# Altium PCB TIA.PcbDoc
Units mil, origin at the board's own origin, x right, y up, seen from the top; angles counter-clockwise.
Board outline 6000 x 4000 mil, 4 copper layers (Top Layer, GND, POWER, Bottom Layer), stack 23.756 mil thick; 19 components, 10 nets, 50 pads, 17 vias.
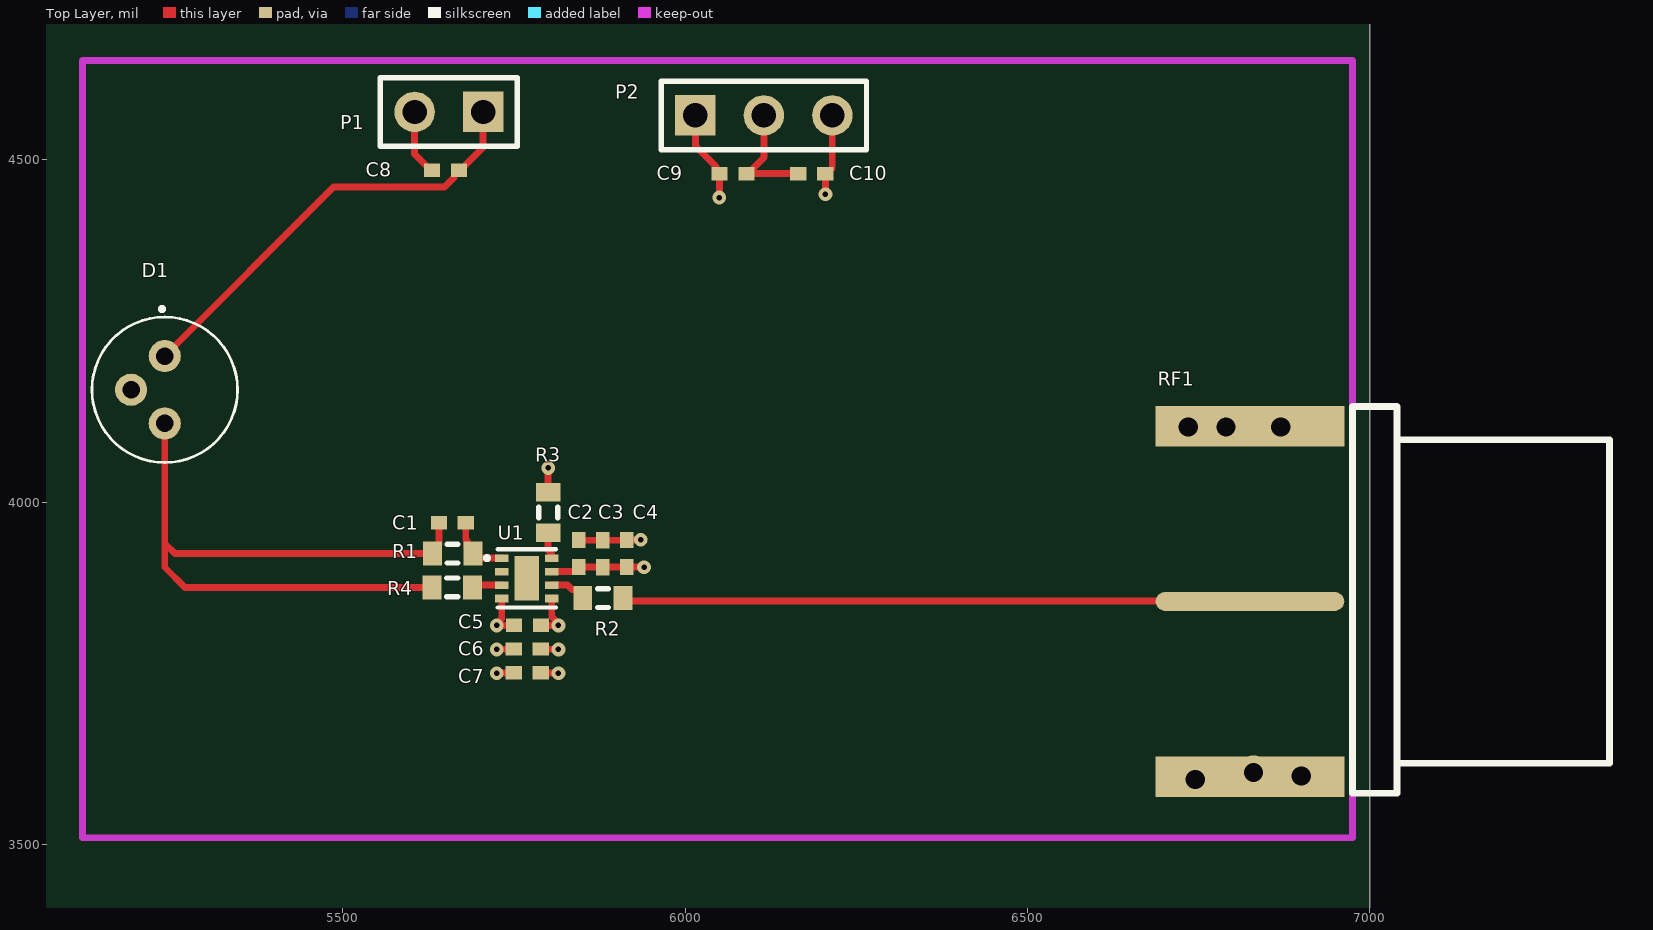
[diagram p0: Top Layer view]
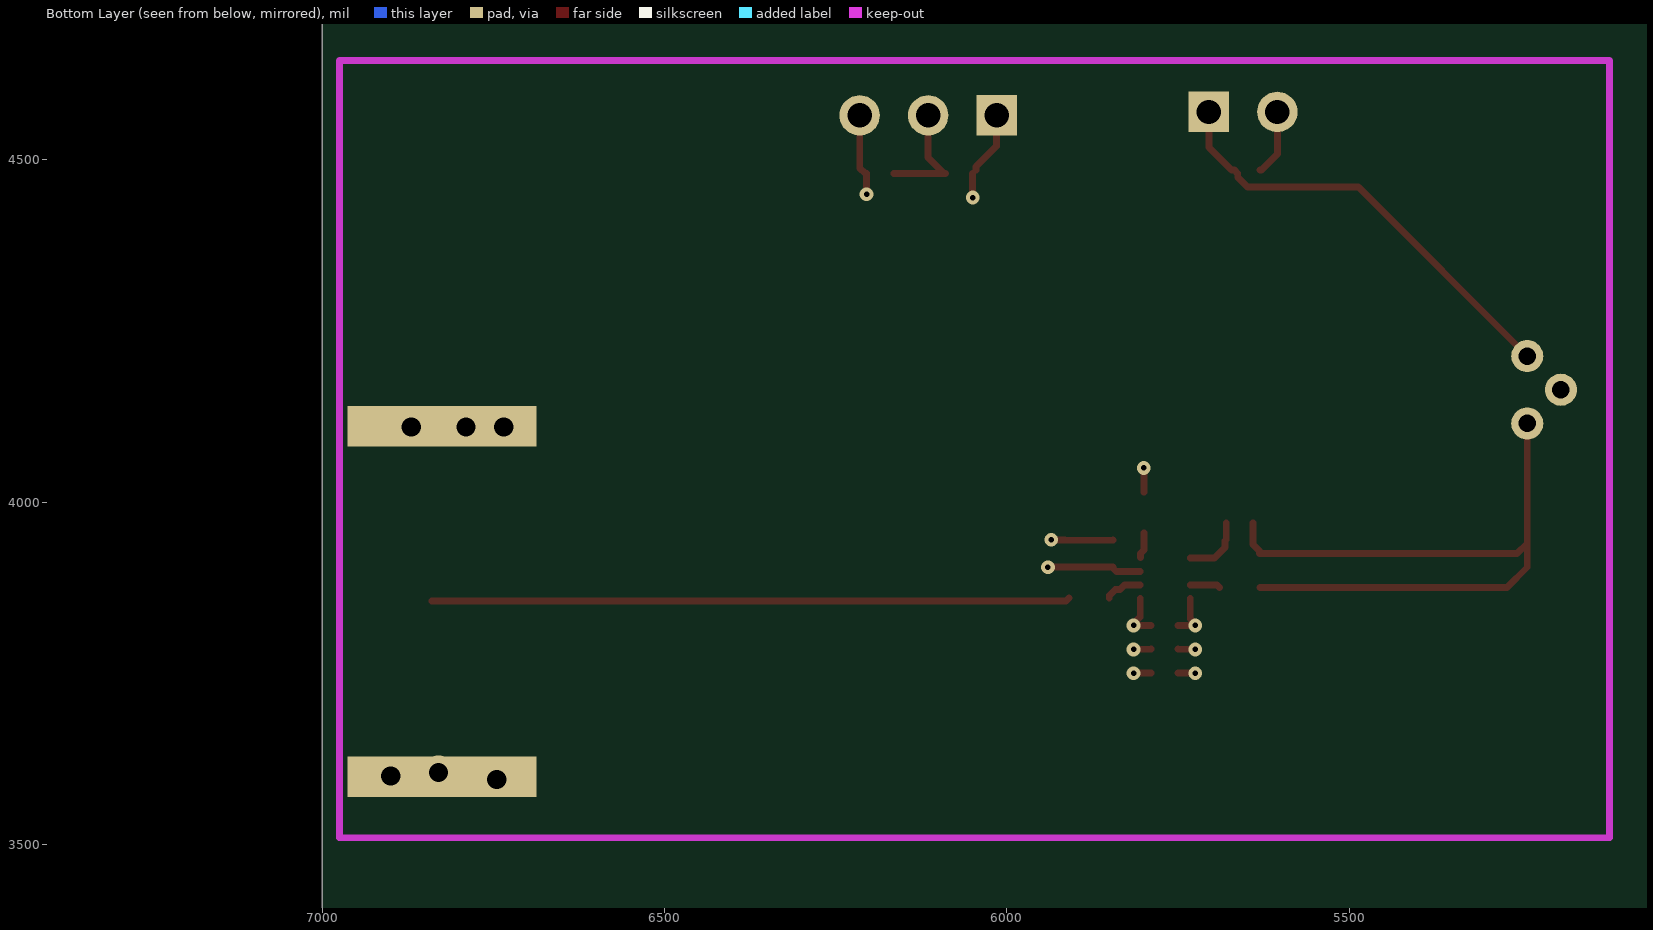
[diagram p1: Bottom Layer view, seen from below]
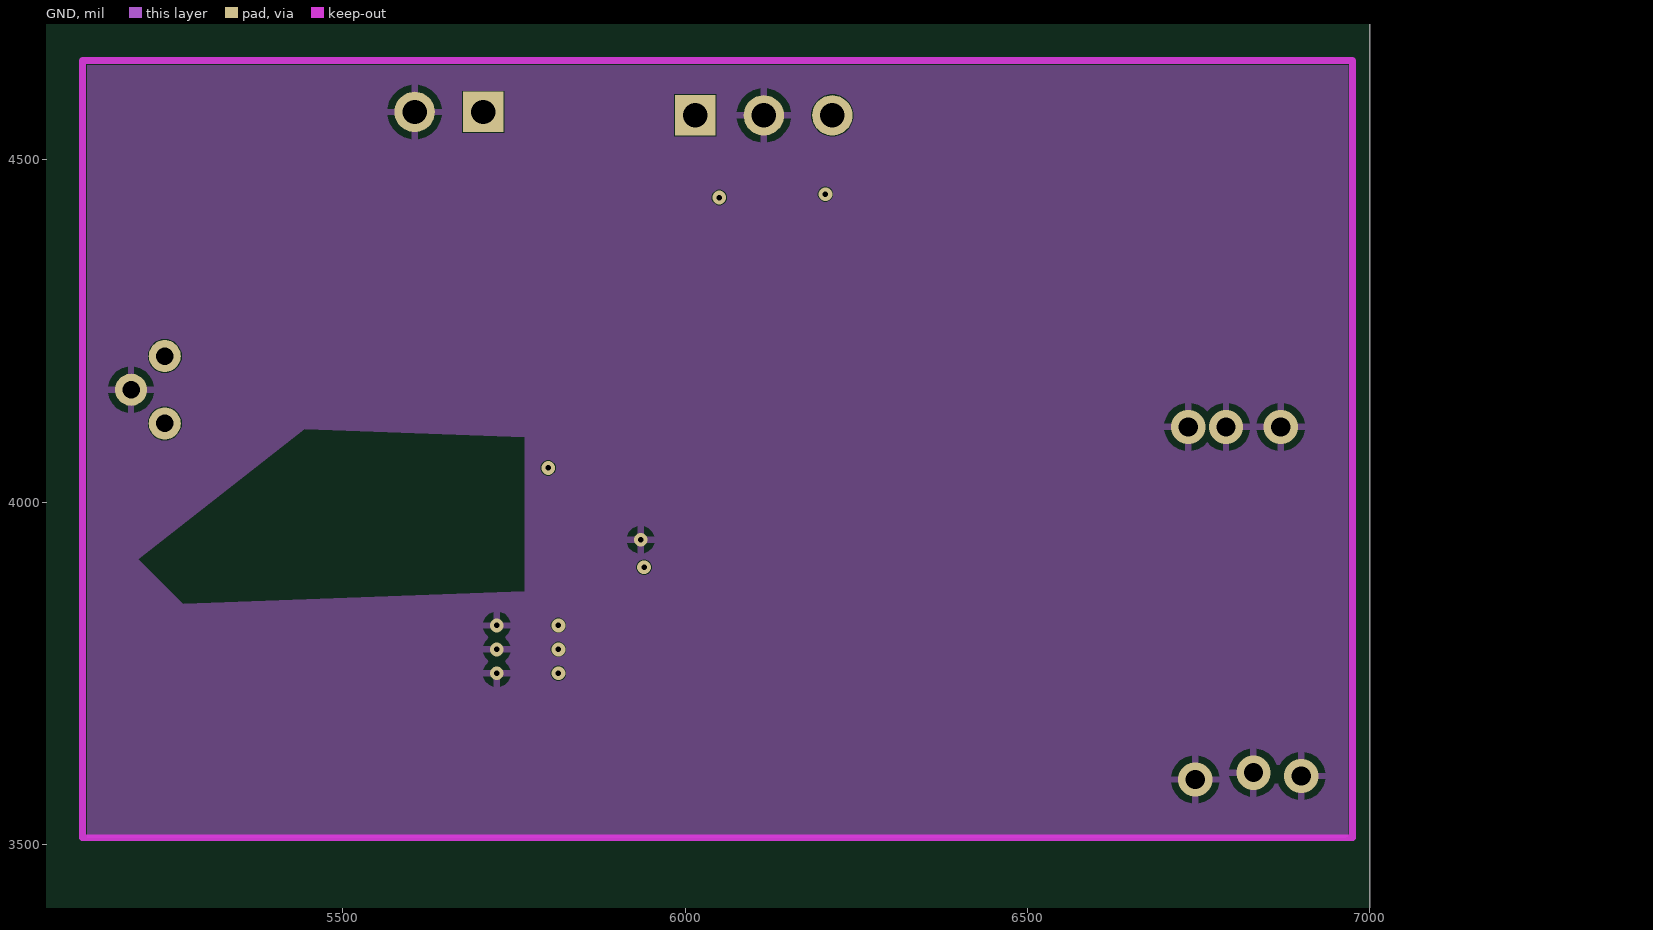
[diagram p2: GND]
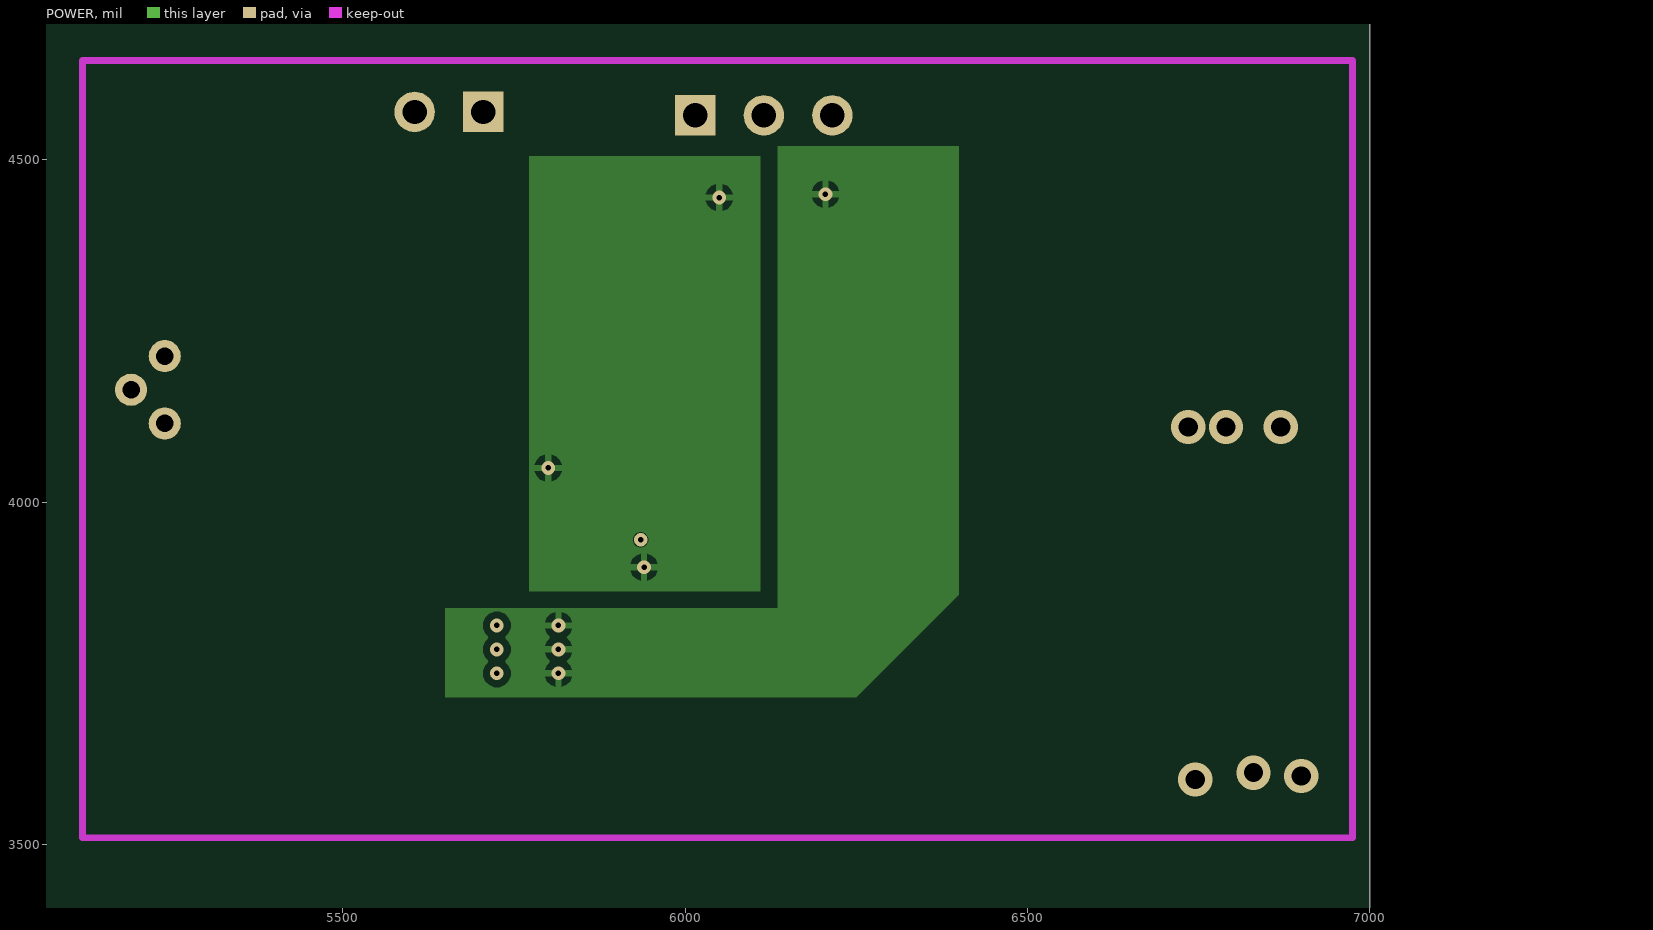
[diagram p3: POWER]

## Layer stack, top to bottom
Top Solder: solder mask 0.4, Solder Resist, Dk 3.5
Top Layer: signal copper 1.4
Dielectric 2: prepreg 2.8, PP-006, Dk 4.1
GND: signal copper 1.378
Dielectric 1: dielectric 12.6, FR-4, Dk 4.8
POWER: signal copper 1.378
Dielectric 3: prepreg 2.8, PP-006, Dk 4.1
Bottom Layer: signal copper 1.4
Bottom Solder: solder mask 0.4, Solder Resist, Dk 3.5

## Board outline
1000,1000 7000,1000 7000,5000 1000,5000

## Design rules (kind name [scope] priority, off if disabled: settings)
Clearance [All] p1: gap=0.5 ignorepadtopadclearanceinfootprint=FALSE
MinimumSolderMaskSliver [All] p1: minsoldermaskwidth=0
PolygonConnect [All] p1: connectstyle=Relief reliefconductorwidth=10 reliefentries=4 polygonreliefangle="90 Angle" airgapwidth=10
RoutingVias [All] p1: holewidth=28 width=50 viastyle="Through Hole" minholewidth=28 minwidth=50 maxholewidth=28 maxwidth=50
SilkToSilkClearance [All] p1: silktosilkclearance=0
SilkToSolderMaskClearance [IsPad] p1: minsilkscreentomaskgap=0 clearancetoexposedcopper=TRUE
SolderMaskExpansion [All] p1: expansion=4 istentingtop=FALSE
Width [All] p1: maxlimit=10 minlimit=10 preferedwidth=10
27 further rules are at their usual default settings.

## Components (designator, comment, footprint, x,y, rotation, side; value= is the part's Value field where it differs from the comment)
C1 "Cap Semi" 0402 5660,3970 r0 top value=0.35pF
C2 "Cap Semi" 0402 5845,3925 r90 top value=0.1uF
C3 "Cap Semi" 0402 5880,3924.68 r90 top value=1uF
C4 "Cap Semi" 0402 5915,3925 r90 top value=10uF
C5 "Cap Semi" 0402 5770,3820 r180 top value=0.1uF
C6 "Cap Semi" 0402 5769.53,3785.59 r180 top value=1uF
C7 "Cap Semi" 0402 5769.53,3750.59 r180 top value=10uF
C8 "Cap Semi" 0402 5650,4485 r0 top value=10uF
C9 "Cap Semi" 0402 6070,4480 r180 top value=10uF
C10 "Cap Semi" 0402 6185,4480 r180 top value=10uF
D1 "FDS015" FDS015 5240,4213.43 r90 top
P1 "Header 2" HDR1X2 5705,4570 r180 top
P2 "Header 3" HDR1X3 6015,4565 r0 top
R1 "Res3" J1-0603 5660.47,3925 r0 top value=500
R2 "Res3" J1-0603 5880,3860 r0 top value=40
R3 "Res3" J1-0603 5800,3985 r90 top value=10k
R4 "Res3" J1-0603 5660,3875.59 r0 top value=10
RF1 "142-0701-851_C6364219" SMA-SMD_142-0701-851_C9900042627 6825,3855 r270 top
U1 "OPA855IDSGR" OPA855IDSGROPA855IDSGR 5768.8,3888.86 r270 top

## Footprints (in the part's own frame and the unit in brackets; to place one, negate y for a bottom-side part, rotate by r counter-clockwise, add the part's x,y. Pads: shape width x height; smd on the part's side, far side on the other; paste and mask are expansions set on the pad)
0402 [mm] "Chip Capacitor, Body 1.0x0.5mm, IPC High Density"
  rect 0.6x0.5 smd: 1(-0.5,0) 2(0.5,0)
  body extent -0.55,-0.3 0.55,0.3, height 1.3
FDS015 [mm]
  round 1.192 hole 0.65: 1(0,0) 2(-1.25,1.25) 3(-2.5,0)
  silkscreen extent -3.95,-2.7 1.8,2.7
HDR1X2 [mm] "Connector; Header; 2 Position"
  rect 1.5x1.5 hole 0.9: 1(0,0)
  round 1.5 hole 0.9: 2(2.54,0)
  silkscreen extent -1.27,-1.27 3.81,1.27
HDR1X3 [mm] "Connector; Header; 3 Position"
  rect 1.5x1.5 hole 0.9: 1(0,0)
  round 1.5 hole 0.9: 2(2.54,0) 3(5.08,0)
  silkscreen extent -1.27,-1.27 6.35,1.27
J1-0603 [mm] "Chip Resistor, Body 1.6x0.8mm, IPC High Density"
  rect 0.7x0.9 smd: 1(-0.75,0) 2(0.75,0)
  silkscreen extent -0.2,-0.35 0.2,0.35, body extent -0.85,-0.48 0.85,0.48, height 0.9
OPA855IDSGROPA855IDSGR [mm]
  rect 0.28x0.505 smd paste+0.051: 1(-0.75,-0.928) 2(-0.25,-0.928) 3(0.25,-0.928) 4(0.75,-0.928) 5(0.75,0.928) 6(0.25,0.928) 7(-0.25,0.928) 8(-0.75,0.928)
  rect 1.65x0.9 smd paste+0.051: 9(0,0)
  silkscreen extent -1.08,-1.55 1.08,1.08
SMA-SMD_142-0701-851_C9900042627 [mm]
  rect 1.5x7 smd paste+0 mask+0.05: 1(-6.5,0) 2(6.5,0)
  rect 1.5x7 smd far side paste+0 mask+0.05: 3(-6.5,0) 4(6.5,0)
  oval 0.7x7 smd paste+0 mask+0.05: 5(0,0)
  silkscreen extent -7.24,3.81 7.11,13.33

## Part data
C1 C2 C3 C4 C5 C6 C7 C8 C9 C10: "Capacitor (Semiconductor SIM Model)"
D1: "Si Photodiode, 35 ps Rise Time, 400 - 1100 nm, 150 m Active Area", Manufacturer_Name=Thorlabs
P1: "Header, 2-Pin"
P2: "Header, 3-Pin"
R1 R2 R3 R4: "Resistor"

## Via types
v1: diameter 20, hole 7.99, Top Layer to Bottom Layer, 11 vias
v2: diameter 50, hole 28, Top Layer to Bottom Layer, 6 vias

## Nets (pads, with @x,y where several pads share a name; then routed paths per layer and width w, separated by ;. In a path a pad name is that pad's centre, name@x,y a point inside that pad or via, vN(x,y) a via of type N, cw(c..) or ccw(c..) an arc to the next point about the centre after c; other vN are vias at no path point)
+2V5: C2.1 C3.1 C4.1 C9.2 P2.1 R3.2 U1.7 | length 302.1
  Top Layer w10: R3.2 v1(5800,4050) ; U1.7 5840.16,3898.7 5845,3903.54 C2.1 5845.16,3905.16 5879.84,3905.16 C3.1 5880.16,3905.16 5914.84,3905.16 C4.1 5915.16,3905.16 5939.84,3905.16 v1(5940,3905) ; P2.1 6015,4520 6045,4490 C9.2@6045,4484.84 ; v1(6050,4445) 6050.16,4445.16 6050.16,4479.84 C9.2 ; C9.2@6050,4480 C9.2@6050.08,4480
+5: C8.2 D1.1 P1.1 | length 646.2
  Top Layer w10: D1.1 5486.73,4460.16 5648.34,4460.16 5662.87,4474.69 5662.87,4480.16 5667.72,4485 5671.65,4485 5705,4518.35 P1.1
-2V5: C5.1 C6.1 C7.1 C10.1 P2.3 U1.5 | length 241.3
  Top Layer w10: C7.1 5789.51,3750.3 5814.7,3750.3 v1(5815,3750) ; C6.1 5789.51,3785.3 5814.7,3785.3 v1(5815,3785) ; C5.1 v1(5815,3820) 5815,3822.71 5805.32,3832.39 U1.5 ; v1(6205,4450) 6204.84,4450.16 6204.84,4479.84 C10.1 6206.65,4480 6215,4488.35 P2.3
GND: C2.2 C3.2 C4.2 C5.2 C6.2 C7.2 C8.1 C9.1 C10.2 D1.2 P1.2 P2.2 RF1.1 RF1.2 RF1.3 RF1.4 U1.4 | length 475.2
  Top Layer w10: P1.2 5605,4508.35 5628.35,4485 C8.1 ; v1(5725,3750) 5725.3,3750.3 5749.55,3750.3 C7.2 ; v1(5725,3785) 5725.3,3785.3 5749.55,3785.3 C6.2 ; U1.4 5732.28,3829.98 5725,3822.71 v1(5725,3820) C5.2 ; C2.2 5845.16,3944.53 5879.84,3944.53 C3.2 5880.16,3944.53 5914.84,3944.53 C4.2 5915.16,3944.84 5934.84,3944.84 v1(5935,3945) ; C9.1 C9.1@6091.65,4480 ; P2.2 6115,4503.35 C9.1@6091.65,4480 ; C10.2 C9.1@6091.65,4480
  other v2: 6745,3595 6900,3600 6830,3605 6735,4110 6790,4110 6870,4110
NetC1_1: C1.1 D1.3 R1.1 R4.1 | length 1058.7
  Top Layer w10: D1.3 5240,3940 ; R4.1 5269.41,3875.59 5240,3905 5240,3925 5240,3940 ; C1.1 5640.31,3938.31 5630.94,3928.94 R1.1 5255,3925 5240,3940
NetC1_2: C1.2 R1.2 U1.1 | length 94.3
  Top Layer w10: C1.2 5679.69,3945.16 5681.22,3943.62 5681.22,3933.78 R1.2 5696.61,3918.39 U1.1
NetR2_1: R2.1 U1.6 | length 55.3
  Top Layer w10: U1.6 5828.43,3879.02 5834.73,3872.72 5841.69,3872.72 5850.47,3863.94 R2.1
NetR2_2: R2.2 RF1.5 | length 932.2
  Top Layer w10: R2.2 5913.62,3855.91 RF1.5@6840,3855.91
NetR3_1: R3.1 U1.8 | length 38.3
  Top Layer w10: R3.1 5800,3930 5805,3925 U1.8@5805,3919.21
NetR4_2: R4.2 U1.3 | length 44.2
  Top Layer w10: R4.2 5692.95,3879.02 U1.3
pads on no net: U1.2 U1.9

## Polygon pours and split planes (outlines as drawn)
+2V5 on POWER "+2V5_L03_P002" (solid, pour order 2): 6110,4505 6110,3870 5772.5,3870 5772.5,4505
-2V5 on POWER "-2V5_L03_P003" (solid, pour order 3): 5650,3845 5650,3715 5675,3715 6250,3715 6400,3865 6400,4520 6135,4520 6135,3845
GND on GND "GND_L02_P000" (solid, pour order 0): 5125,4640 5130,4645 6970,4645 6970,3505 6965,3510 5125,3510

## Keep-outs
Keep-Out Layer:
  lines w10: 5120,3510 6975,3510 6975,4645 5120,4645 5120,3510

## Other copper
GND:
  pour cut-out: 5444.69,4106.55 5202.19,3916.55 5267.19,3851.55 5765,3870 5765,4095
  pour cut-out: 5340,4005 5335,4000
